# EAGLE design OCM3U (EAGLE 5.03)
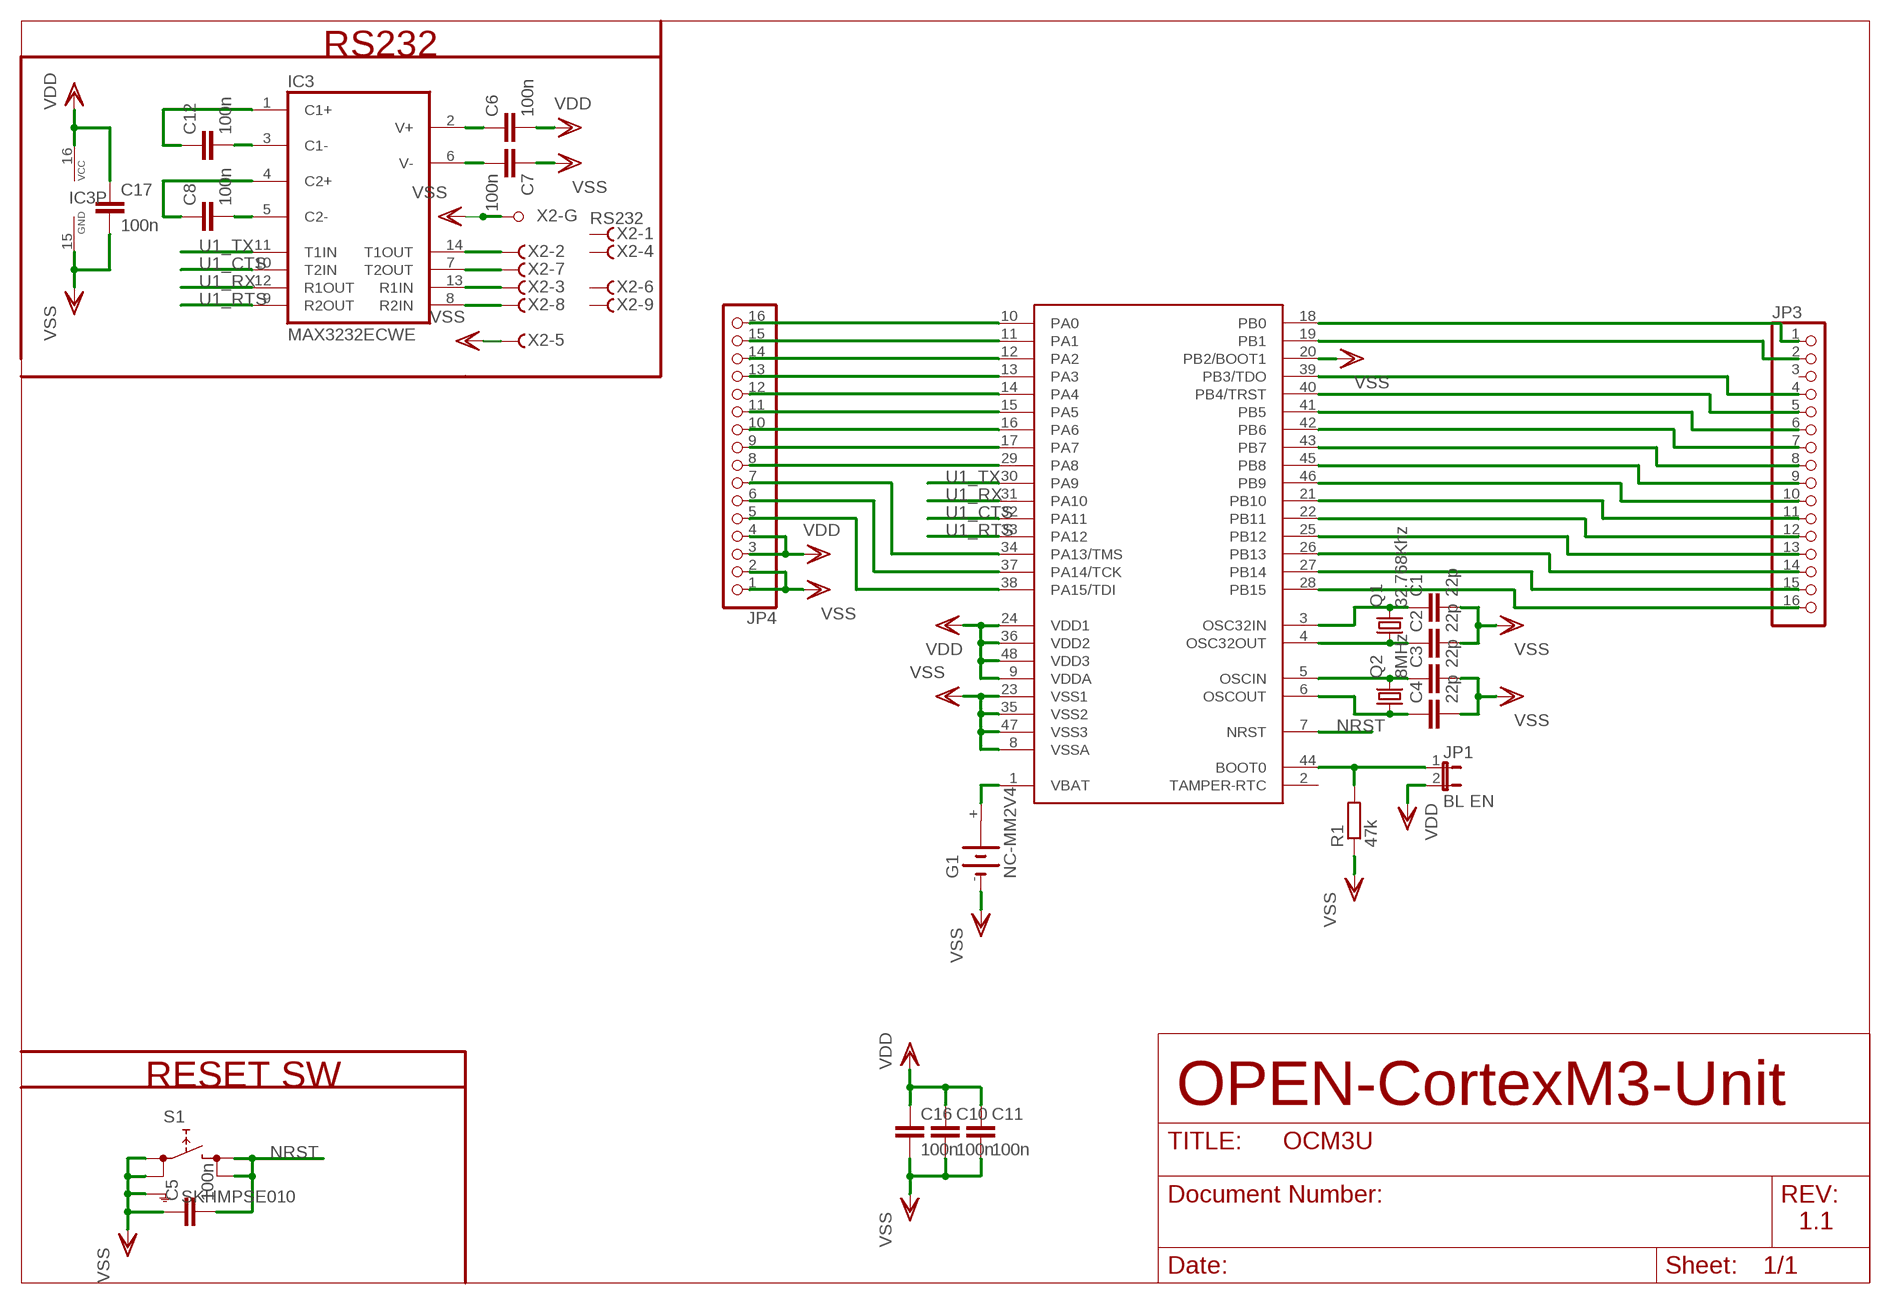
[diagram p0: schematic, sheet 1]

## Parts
C1  22p  C-EUC0805  [C0805]
C2  22p  C-EUC0805  [C0805]
C3  22p  C-EUC0805  [C0805]
C4  22p  C-EUC0805  [C0805]
C5  100n  C-EUC0805  [C0805]
C6  100n  C-EUC0805  [C0805]
C7  100n  C-EUC0805  [C0805]
C8  100n  C-EUC0805  [C0805]
C10  100n  C-EUC0805  [C0805]
C11  100n  C-EUC0805  [C0805]
C12  100n  C-EUC0805  [C0805]
C16  100n  C-EUC0805  [C0805]
C17  100n  C-EUC0805  [C0805]
G1  NC-MM2V4  [NC-MM]
IC3  MAX3232ECWE  MAX232ECWE  [SO16L]
JP1  BL EN  JP1E  [JP1]
JP3  PINHD-1X16  [1X16]
JP4  PINHD-1X16  [1X16]
Q1  32.768Khz  CRYSTALHC49UP  [HC49UP]
Q2  8MHz  CRYSTALHC49UP  [HC49UP]
R1  47k  R-EU_R0805  [R0805]
S1  SKHMPSE010  [SKHMPXE010]
U$1  STM32F101C8T6  [LQFP48]
X2  RS232  F09HPS  [F09HP]

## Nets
N$1: G1.+ U$1.1(VBAT)
N$2: JP1.1 R1.2 U$1.44(BOOT0)
N$4: C1.1 Q1.2 U$1.3(OSC32IN)
N$5: C2.1 Q1.1 U$1.4(OSC32OUT)
N$6: C3.1 Q2.2 U$1.5(OSCIN)
N$7: C4.1 Q2.1 U$1.6(OSCOUT)
N$8: IC3.13(R1IN) X2.3(-3:F)
N$9: IC3.14(T1OUT) X2.2(-2:F)
N$10: IC3.7(T2OUT) X2.7(-7:F)
N$11: IC3.8(R2IN) X2.8(-8:F)
N$12: C6.1 IC3.2(V+)
N$13: C7.2 IC3.6(V-)
N$14: C12.2 IC3.3(C1-)
N$15: C12.1 IC3.1(C1+)
N$16: C8.1 IC3.4(C2+)
N$17: C8.2 IC3.5(C2-)
N$18: JP3.16 U$1.28(PB15)
N$19: JP3.15 U$1.27(PB14)
N$20: JP3.9 U$1.45(PB8)
N$21: JP3.14 U$1.26(PB13)
N$22: JP3.13 U$1.25(PB12)
N$23: JP3.12 U$1.22(PB11)
N$24: JP3.11 U$1.21(PB10)
N$25: JP3.10 U$1.46(PB9)
N$27: JP3.8 U$1.43(PB7)
N$28: JP3.7 U$1.42(PB6)
N$29: JP3.6 U$1.41(PB5)
N$30: JP3.2 U$1.19(PB1)
N$31: JP3.1 U$1.18(PB0)
N$32: JP4.16 U$1.10(PA0)
N$33: JP4.15 U$1.11(PA1)
N$34: JP4.14 U$1.12(PA2)
N$35: JP4.13 U$1.13(PA3)
N$36: JP4.12 U$1.14(PA4)
N$37: JP4.11 U$1.15(PA5)
N$38: JP4.10 U$1.16(PA6)
N$39: JP4.9 U$1.17(PA7)
N$40: JP4.8 U$1.29(PA8)
N$44: JP3.5 U$1.40(PB4/TRST)
N$45: JP3.4 U$1.39(PB3/TDO)
N$46: JP4.7 U$1.34(PA13/TMS)
N$47: JP4.6 U$1.37(PA14/TCK)
N$48: JP4.5 U$1.38(PA15/TDI)
NRST: C5.2 S1.3(2.1) S1.4(2.2) U$1.7(NRST)
U1_CTS: IC3.10(T2IN) U$1.32(PA11)
U1_RTS: IC3.9(R2OUT) U$1.33(PA12)
U1_RX: IC3.12(R1OUT) U$1.31(PA10)
U1_TX: IC3.11(T1IN) U$1.30(PA9)
VDD: C6.2 C10.1 C11.1 C16.1 C17.1 IC3.16(VCC) JP1.2 JP4.3 JP4.4 U$1.9(VDDA) U$1.24(VDD1) U$1.36(VDD2) U$1.48(VDD3)
VSS: C1.2 C2.2 C3.2 C4.2 C5.1 C7.1 C10.2 C11.2 C16.2 C17.2 G1.- IC3.15(GND) JP4.1 JP4.2 R1.1 S1.1(1.1) S1.2(1.2) S1.5(SH) U$1.8(VSSA) U$1.20(PB2/BOOT1) U$1.23(VSS1) U$1.35(VSS2) U$1.47(VSS3) X2.5(-5:F) X2.G1(-G:G1) X2.G2(-G:G2)
Unconnected: G1.+@1(+) JP3.3 U$1.2(TAMPER-RTC) X2.1(-1:F) X2.4(-4:F) X2.6(-6:F) X2.9(-9:F)

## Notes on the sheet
- RS232
- RESET SW
- OPEN-CortexM3-Unit
- 1.1

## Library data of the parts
C1-C8 C10-C12 C16 C17 = rcl:C-EU: CAPACITOR, European symbol
G1 = battery:NC-MM2V4: NC ACCU Sonnenschein Mini-Memo NC-MM 2.4 to 4.8 R5 Sonnenschein
IC3 = maxim:MAX232ECWE: RS232 TRANSEIVER
JP1 = jumper:JP1E: JUMPER
JP3 JP4 = pinhead:PINHD-1X16: PIN HEADER
Q1 Q2 = crystal:CRYSTAL: CRYSTAL
R1 = resistor:R-EU_: RESISTOR, European symbol
S1 = switch:SKHMP*E010: 6.2 X 6.5mm TACT Switch (SMD) Source: http://www3.alps.co.jp/WebObjects/catalog.woa/PDF/E/Switch/Tact/SKHM/SKHM.PDF
U$1 = stm32F101xx:STM32F101C8T6
X2 = con-subd:F09HPS: SUB-D

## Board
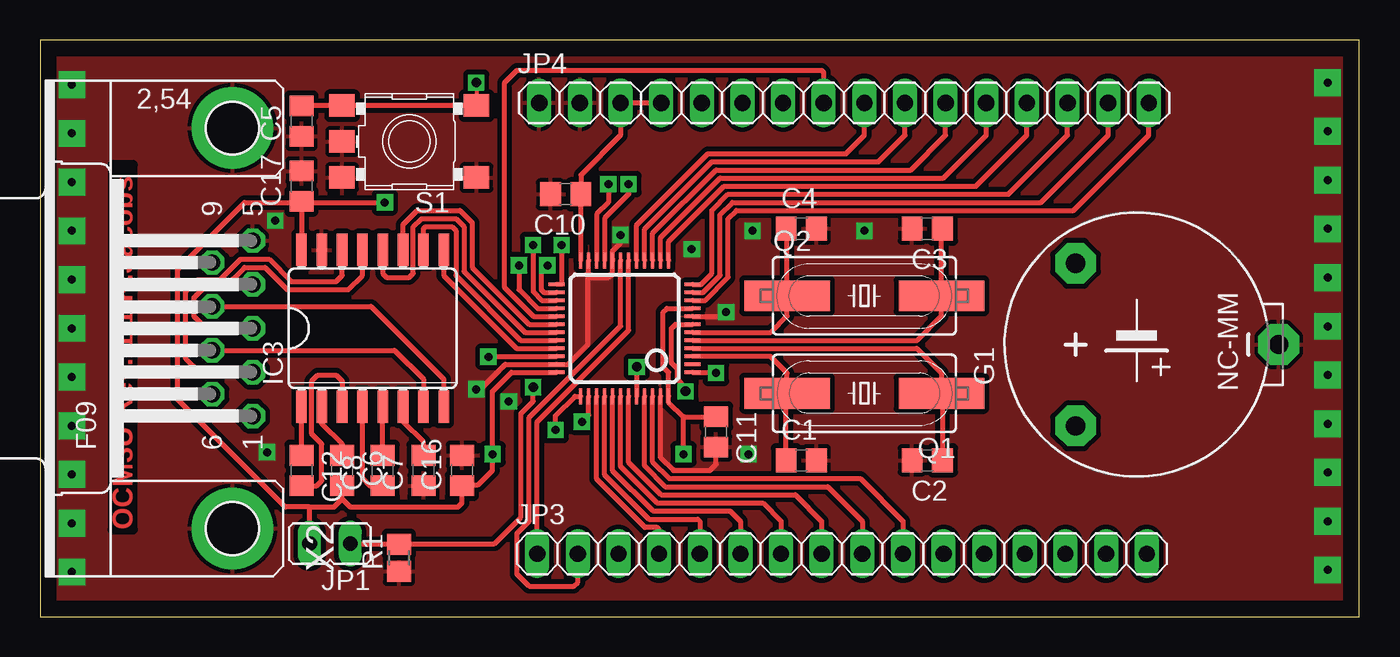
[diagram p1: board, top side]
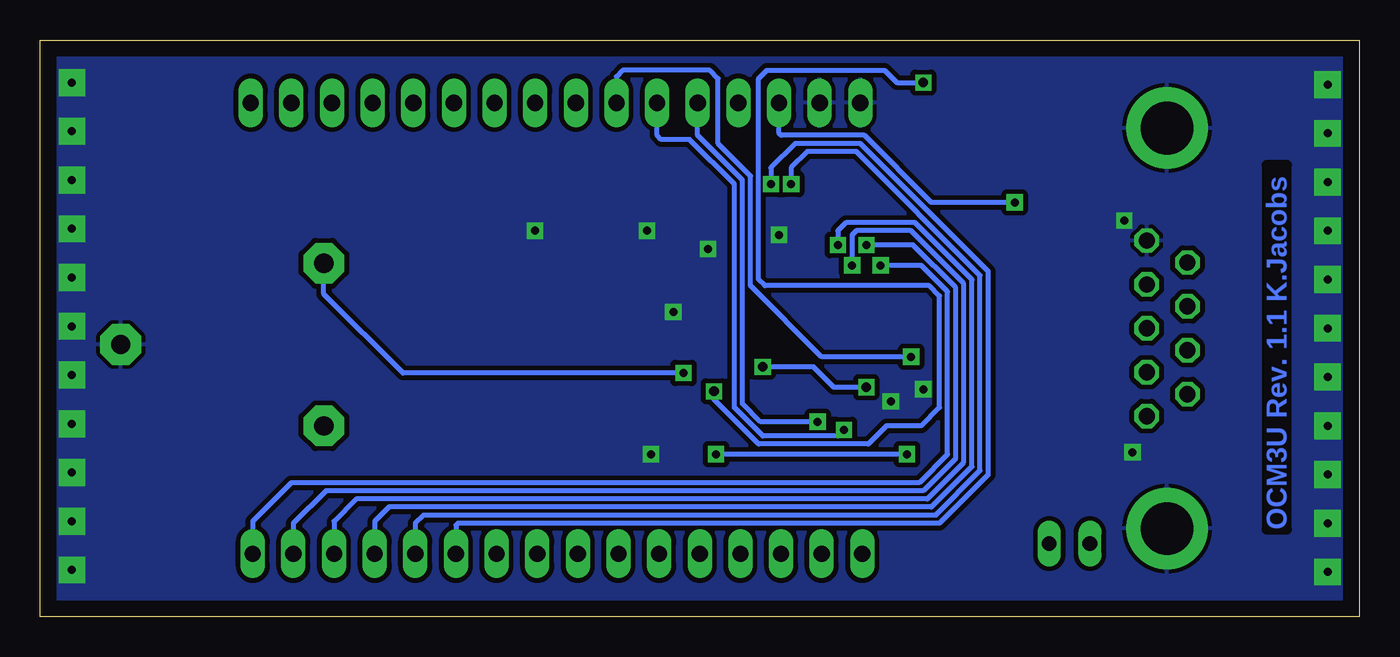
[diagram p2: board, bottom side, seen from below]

Size 82.47 x 36.06 mm. Coordinates in mm from the lower left corner, seen from the top.
Outline: 0,0 82.47,0 82.47,36.06 0,36.06 0,0
Copper layers (1*16): Top 0.035mm / dielectric 1.5mm / Bottom 0.035mm
Design rules "default": minimum track width 10mil, minimum drill 24mil, track to track 8mil, track to pad 8mil, pad to pad 8mil, via to via 8mil, smd to smd 8mil, copper to edge 40mil, drill to drill 8mil, minimum pad ring 10mil, minimum via ring 8mil, stop-mask expansion 4mil, vias tented up to drill 0mil, thermal gap 10mil

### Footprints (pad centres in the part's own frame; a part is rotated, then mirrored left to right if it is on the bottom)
C0805 = smd 1.3 x 1.5: 1 -0.95,0; 2 0.95,0
NC-MM = drill 1.194 pad 2.54 octagon: + 5.08,3.81; +@1 -5.08,3.81; - 0,-8.89
SO16L = smd 0.66 x 2.032: 1 -4.445,-4.902; 2 -3.175,-4.902; 3 -1.905,-4.902; 4 -0.635,-4.902; 5 0.635,-4.902; 6 1.905,-4.902; 7 3.175,-4.902; 8 4.445,-4.902; 9 4.445,4.902; 10 3.175,4.902; 11 1.905,4.902; 12 0.635,4.902; 13 -0.635,4.902; 14 -1.905,4.902; 15 -3.175,4.902; 16 -4.445,4.902
JP1 = drill 0.914 long: 1 0,-1.27; 2 0,1.27
1X16 = drill 1.016 long: 1 -19.05,0; 2 -16.51,0; 3 -13.97,0; 4 -11.43,0; 5 -8.89,0; 6 -6.35,0; 7 -3.81,0; 8 -1.27,0; 9 1.27,0; 10 3.81,0; 11 6.35,0; 12 8.89,0; 13 11.43,0; 14 13.97,0; 15 16.51,0; 16 19.05,0
HC49UP = smd 5.334 x 1.93: 1 -4.826,0; 2 4.826,0
R0805 = smd 1.3 x 1.5: 1 -0.85,0; 2 0.85,0
SKHMPXE010 = smd 1.6 x 1.4: 1 -4.2,2.25; 2 4.2,2.25; 3 -4.2,-2.25; 4 4.2,-2.25; 5 4.2,0
LQFP48 = smd 0.2 x 1: 1 -2.75,-4.25; 2 -2.25,-4.25; 3 -1.75,-4.25; 4 -1.25,-4.25; 5 -0.75,-4.25; 6 -0.25,-4.25; 7 0.25,-4.25; 8 0.75,-4.25; 9 1.25,-4.25; 10 1.75,-4.25; 11 2.25,-4.25; 12 2.75,-4.25; 25 2.75,4.25; 26 2.25,4.25; 27 1.75,4.25; 28 1.25,4.25; 29 0.75,4.25; 30 0.25,4.25; 31 -0.25,4.25; 32 -0.75,4.25; 33 -1.25,4.25; 34 -1.75,4.25; 35 -2.25,4.25; 36 -2.75,4.25 | smd 1 x 0.2: 13 4.25,-2.75; 14 4.25,-2.25; 15 4.25,-1.75; 16 4.25,-1.25; 17 4.25,-0.75; 18 4.25,-0.25; 19 4.25,0.25; 20 4.25,0.75; 21 4.25,1.25; 22 4.25,1.75; 23 4.25,2.25; 24 4.25,2.75; 37 -4.25,2.75; 38 -4.25,2.25; 39 -4.25,1.75; 40 -4.25,1.25; 41 -4.25,0.75; 42 -4.25,0.25; 43 -4.25,-0.25; 44 -4.25,-0.75; 45 -4.25,-1.25; 46 -4.25,-1.75; 47 -4.25,-2.25; 48 -4.25,-2.75
F09HP = drill 1.016 octagon: 1 -5.486,-1.27; 2 -2.743,-1.27; 3 0,-1.27; 4 2.743,-1.27; 5 5.486,-1.27; 6 -4.115,1.27; 7 -1.372,1.27; 8 1.372,1.27; 9 4.115,1.27 | drill 3.302 pad 5.08 round: G1 -12.522,0; G2 12.522,0

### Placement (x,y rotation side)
C1  47.59,9.77 0 top
C2  55.46,9.77 180 top
C3  55.46,24.25 180 top
C4  47.59,24.25 0 top
C5  16.34,30.98 90 top
C6  18.89,9.14 270 top
C7  23.96,9.14 90 top
C8  21.43,9.14 90 top
C10  32.86,26.41 180 top
C11  42.25,11.55 270 top
C12  16.34,9.14 270 top
C16  26.38,9.14 90 top
C17  16.34,26.92 90 top
G1  68.54,17.01 90 top
IC3  20.79,18.03 0 top
JP1  18.12,4.57 90 top
JP3  50.13,3.93 0 top
JP4  50.25,32.13 0 top
Q1  51.52,13.96 180 top
Q2  51.52,20.06 0 top
R1  22.44,3.68 90 top
S1  23.08,29.71 180 top
U$1  36.54,18.03 90 top
X2  12.03,18.03 90 top

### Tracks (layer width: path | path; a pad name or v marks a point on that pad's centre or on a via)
N$1  (via drill 0.5 pad 1.02)
  Top 0.305: U$1.1 42.21,15.28 v42.25,15.23
  Bottom 0.305: v42.25,15.23 59.78,15.23 64.73,20.19 G1.+
N$2  (via drill 0.6)
  Top 0.305: JP1.1 22.44,4.57 | 22.44,4.57 R1.2 | v37.3,15.62 37.3,13.78 U$1.44 | 22.44,4.57 28.41,4.57 30.06,6.22 30.06,12.7 30.82,13.46 v30.82,14.35
  Bottom 0.305: v30.82,14.35 32.86,14.35 34.12,15.62 v37.3,15.62
N$4
  Top 0.305: U$1.3 45.65,16.28 46.7,15.23 46.7,14.09 46.83,13.96 Q1.2 46.57,13.96 46.64,13.9 C1.1
N$5
  Top 0.305: U$1.4 54.81,16.78 56.35,15.23 56.35,14.09 | 56.35,13.71 Q1.1 56.35,14.09 | C2.1 56.41,14.03 56.35,14.09
N$6
  Top 0.305: U$1.5 54.84,17.28 56.35,18.79 Q2.2 | Q2.2 56.22,20.19 | C3.1 56.1,24.25 56.35,24 Q2.2
N$7
  Top 0.305: U$1.6 45.69,17.78 46.7,18.79 Q2.1 | Q2.1 46.7,20.19 | C4.1 46.7,24.25 Q2.1
N$8
  Top 0.254: IC3.13 20.16,23.11
  Top 0.305: X2.3 10.38,18.03 9.61,18.79 9.61,19.93 10.25,20.57 11.52,20.57 12.79,21.84 14.06,21.84 15.46,20.44 19.27,20.44 20.16,21.33 IC3.13
N$9
  Top 0.305: X2.2 9.94,15.29 9.11,16.12 9.11,20.32 9.87,21.08 11.26,21.08 12.54,22.35 14.31,22.35 15.71,20.95 18.5,20.95 18.89,21.33 IC3.14
N$10
  Top 0.254: IC3.7 23.96,12.95
  Top 0.305: X2.7 22.16,16.66 23.96,14.85 IC3.7
N$11
  Top 0.254: IC3.8 25.24,12.95
  Top 0.305: X2.8 20.69,19.4 25.24,14.85 25.24,13.33 25.36,13.2 IC3.8
N$12
  Top 0.305: IC3.2 17.62,12.06 18.89,10.79 C6.1
N$13
  Top 0.305: IC3.6 22.7,12.19 23.96,10.92 23.96,10.28 23.84,10.15 C7.2
N$14
  Top 0.305: C12.2 17.3,8.19 17.62,8.5 17.62,10.79 16.98,11.42 16.98,14.73 17.36,15.11 18.5,15.11 18.89,14.73 18.89,13.33 19.01,13.2 IC3.3
N$15
  Top 0.305: C12.1 IC3.1
N$16
  Top 0.305: C8.1 20.6,8.19 20.16,8.63 20.16,12.82 20.03,12.95 20.16,13.08 IC3.4
N$17
  Top 0.305: C8.2 IC3.5
N$18  (via drill 0.5 pad 1.02)
  Top 0.305: U$1.28 31.1,19.28 29.93,20.44 v29.93,21.97
  Bottom 0.305: v29.93,21.97 27.39,21.97 25.74,20.32 25.74,10.15 27.52,8.38 66.76,8.38 69.18,5.96 JP3.16
N$19  (via drill 0.5 pad 1.02)
  Top 0.305: U$1.27 31.36,19.78 30.82,20.32 v30.82,23.24
  Bottom 0.305: v30.82,23.24 27.9,23.24 25.24,20.57 25.24,9.9 27.27,7.87 64.6,7.87 66.64,5.84 JP3.15
N$20
  Top 0.305: U$1.45 37.79,9.41 39.08,8.12 49.24,8.12 51.4,5.96 JP3.9 51.4,3.81
N$21  (via drill 0.5 pad 1.02)
  Top 0.305: U$1.26 31.49,20.28 31.33,20.44 31.33,21.97 v31.71,21.97
  Bottom 0.305: v31.71,21.97 31.71,23.87 31.46,24.12 28.03,24.12 24.73,20.82 24.73,9.65 27.01,7.36 62.7,7.36 64.1,5.96 JP3.14
N$22  (via drill 0.5 pad 1.02)
  Top 0.305: U$1.25 32.6,20.78 v32.6,23.24
  Bottom 0.305: v32.6,23.24 32.6,24.12 32.09,24.63 27.78,24.63 24.22,21.08 24.22,9.39 26.76,6.85 60.67,6.85 61.56,5.96 61.56,4.19 61.68,4.06 JP3.13
N$23  (via drill 0.5 pad 1.02)
  Top 0.305: U$1.22 34.79,25.17 35.52,25.9 v35.52,27.05
  Bottom 0.305: v35.52,27.05 35.52,28.06 34.51,29.08 31.46,29.08 23.71,21.33 23.71,9.14 26.51,6.35 58.51,6.35 59.02,5.84 JP3.12
N$24  (via drill 0.5 pad 1.02)
  Top 0.305: U$1.21 35.29,24.91 36.79,26.41 v36.79,27.05
  Bottom 0.305: v36.79,27.05 36.79,28.06 35.27,29.59 31.2,29.59 23.2,21.59 23.2,8.88 26.25,5.84 56.35,5.84 56.48,5.71 JP3.11
N$25
  Top 0.305: U$1.46 38.29,9.68 39.33,8.63 51.27,8.63 53.94,5.96 JP3.10 53.94,3.81
N$27
  Top 0.305: U$1.43 36.79,9.65 38.82,7.62 47.21,7.62 48.86,5.96 JP3.8
N$28
  Top 0.305: U$1.42 36.29,9.39 38.57,7.11 45.17,7.11 46.32,5.96 JP3.7
N$29
  Top 0.305: U$1.41 35.79,9.13 38.32,6.6 43.14,6.6 43.78,5.96 JP3.6
N$30
  Top 0.305: U$1.19 36.29,18.16 30.57,12.44 30.57,5.96 29.81,5.2 29.81,2.66 30.57,1.9 33.36,1.9 33.62,2.15 JP3.2
N$31
  Top 0.305: U$1.18 36.79,17.9 31.08,12.19 JP3.1
N$32
  Top 0.305: U$1.10 41.59,19.78 43.02,21.2 43.02,24.89 43.52,25.4 64.6,25.4 69.3,30.09 JP4.16
N$33
  Top 0.305: U$1.11 41.45,20.28 42.51,21.33 42.51,25.14 43.27,25.9 62.57,25.9 66.76,30.09 JP4.15
N$34
  Top 0.305: U$1.12 41.32,20.78 42,21.46 42,25.4 43.02,26.41 60.54,26.41 64.22,30.09 JP4.14
N$35
  Top 0.305: U$1.13 39.29,23.45 42.76,26.92 58.51,26.92 61.68,30.09 JP4.13 61.68,32.25
N$36
  Top 0.305: U$1.14 38.79,23.71 42.51,27.43 56.48,27.43 59.14,30.09 JP4.12
N$37
  Top 0.305: U$1.15 38.29,23.97 42.25,27.94 54.45,27.94 56.6,30.09 JP4.11
N$38
  Top 0.305: U$1.16 37.79,24.23 42,28.44 52.41,28.44 54.06,30.09 JP4.10
N$39
  Top 0.305: U$1.17 37.29,24.49 41.75,28.95 50.38,28.95 51.52,30.09 JP4.9
N$40
  Top 0.305: U$1.29 30.84,18.78 29.05,20.57 29.05,33.4 29.81,34.16 48.86,34.16 48.98,34.03 JP4.8 48.98,32
N$44
  Top 0.305: U$1.40 35.29,8.87 38.06,6.09 41.11,6.09 41.24,5.96 JP3.5
N$45
  Top 0.305: U$1.39 34.79,8.6 37.81,5.58 38.57,5.58 38.7,5.46 JP3.4
N$46  (via drill 0.5 pad 1.02)
  Top 0.305: U$1.34 27.87,16.28 v28.03,16.25
  Bottom 0.305: JP4.7 46.44,33.78 46.06,34.16 40.6,34.16 40.09,33.65 40.09,29.59 38.06,27.55 38.06,20.7 33.62,16.25 v28.03,16.25
N$47  (via drill 0.5 pad 1.02)
  Top 0.305: U$1.37 33.43,13.78 32.22,12.57 v32.22,11.68
  Bottom 0.305: JP4.6 43.9,30.09 43.65,29.84 41.87,29.84 39.08,27.05 39.08,13.08 37.3,11.3 32.6,11.3 v32.22,11.68
N$48  (via drill 0.5 pad 1.02)
  Top 0.305: U$1.38 34.29,12.6 v33.87,12.19
  Bottom 0.305: JP4.5 41.36,30.09 38.57,27.3 38.57,13.33 37.43,12.19 v33.87,12.19
NRST  (via drill 0.6)
  Top 0.254: 27.39,31.96 27.39,32 27.36,31.96 S1.3 27.28,33.39 v27.27,33.4 | C5.2 16.34,32 16.38,31.96
  Top 0.305: U$1.7 39.71,18.28 39.46,18.03 39.46,15.87 39.84,15.49 39.84,14.85 40.35,14.35 v40.35,14.09 | S1.4 19.01,31.96 19.01,32 18.98,31.96 S1.4 | S1.4 16.38,31.96 | S1.3 27.39,31.96 27.52,31.87 27.43,31.96 S1.4
  Bottom 0.305: v27.27,33.4 28.92,33.4 29.68,34.16 37.05,34.16 37.55,33.65 37.55,21.08 37.17,20.7 26.89,20.7 26.25,20.06 26.25,13.08 27.39,11.93 29.55,11.93 30.7,10.79 37.55,10.79 40.35,13.58 v40.35,14.09
U1_CTS
  Top 0.305: U$1.32 30.05,17.28 26,21.33 26,24.12 25.74,24.38 24.09,24.38 23.96,24.25 IC3.10
U1_RTS
  Top 0.254: IC3.9 25.24,22.98
  Top 0.305: U$1.33 29.79,16.78 25.24,21.33 IC3.9
U1_RX
  Top 0.254: 21.43,22.86 IC3.12 21.43,22.98
  Top 0.305: U$1.31 30.31,17.78 26.51,21.59 26.51,24.38 26,24.89 23.84,24.89 23.33,24.38 23.33,21.46 23.08,21.2 21.68,21.2 21.43,21.46 21.43,22.73 21.3,22.86 IC3.12
U1_TX
  Top 0.305: U$1.30 30.57,18.28 27.01,21.84 27.01,24.63 26.25,25.4 23.58,25.4 22.7,24.51 IC3.11 22.7,22.86
VDD  (via drill 0.5 pad 1.02)
  Top 0.254: C11.1 42.25,12.44
  Top 0.305: U$1.24 33.79,26.33 33.87,26.41 C10.1 33.8,27.62 36.28,30.09 JP4.3 JP4.4 | U$1.9 39.19,19.28 38.95,19.05 38.95,15.62 39.29,15.28 U$1.48 39.29,13.37 40.22,12.44 | v40.22,10.15 40.22,12.44 | C11.1 40.28,12.5 40.22,12.44 | U$1.36 29.47,15.28 28.28,14.09 v28.28,10.15 28.28,9.14 27.39,8.25 26.38,8.25 | 18.89,7.36 C6.2 | 18.89,7.36 19.39,6.85 26.12,6.85 26.38,7.11 26.38,8.25 | 26.38,8.25 C16.1 | 18.89,7.36 18.38,6.85 16.85,6.85 | 16.85,6.85 15.33,6.85 8.6,13.58 8.6,21.71 12.79,25.9 16.34,25.9 | 16.34,25.9 C17.1 16.34,26.03 | 16.34,25.9 v21.55,25.9 | IC3.16 16.34,22.86 | IC3.16 16.34,22.98 | 16.34,25.9 IC3.16 | JP1.2 16.85,6.85
  Bottom 0.305: v28.28,10.15 v40.22,10.15 | v21.55,25.9 26.76,25.9 30.95,30.09 36.16,30.09 36.28,30.22 JP4.3 36.28,32.25
VSS  (via drill 0.5 pad 1.02, 0.5 pad 1.68)
  Top 0.254: v42.89,19.05 42.5,18.78 | C11.2 42.25,10.66 | 35.78,21.33 35.79,21.34
  Top 0.305: 34.29,21.33 34.29,21.24 34.25,21.2 35.52,21.2 35.78,21.46 | 34.29,21.33 U$1.23 | 35.78,21.46 35.78,21.33 | 35.78,21.46 35.78,22.35 35.79,22.35 U$1.20 35.79,22.87 36.28,23.36 v36.28,23.87 | U$1.8 42.62,18.78 v42.89,19.05 | 34.29,21.33 34.25,21.33 34.25,17.01 33.02,15.78 U$1.35 29.08,15.78 27.52,14.22 v27.27,14.22 | U$1.47 38.79,9.94 39.59,9.14 41.87,9.14 42.25,9.52 C11.2
  other vias: 80.48,33.4 80.48,30.35 80.48,27.3 80.48,24.25 80.48,21.2 80.48,18.16 80.48,15.11 80.48,12.06 80.48,2.92 80.48,5.96 80.48,9.01 1.99,33.27 1.99,30.22 1.99,27.17 1.99,24.12 1.99,21.08 1.99,18.03 1.99,14.98 1.99,11.93 1.99,2.79 1.99,5.84 1.99,8.88 40.73,22.98 44.54,24.12 51.52,24.12 29.3,13.46 14.69,24.76 14.19,10.28 44.29,10.15
  pour Top (isolate 0.305): -1.94,38.35 84.42,38.35 84.42,-2.29 -1.94,-2.29
  pour Bottom (isolate 0.305): -1.94,38.35 84.42,38.35 84.42,-2.29 -1.94,-2.29

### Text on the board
Top: OCM3U Rev. 1.1 K.Jacobs
Bottom: OCM3U Rev. 1.1 K.Jacobs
